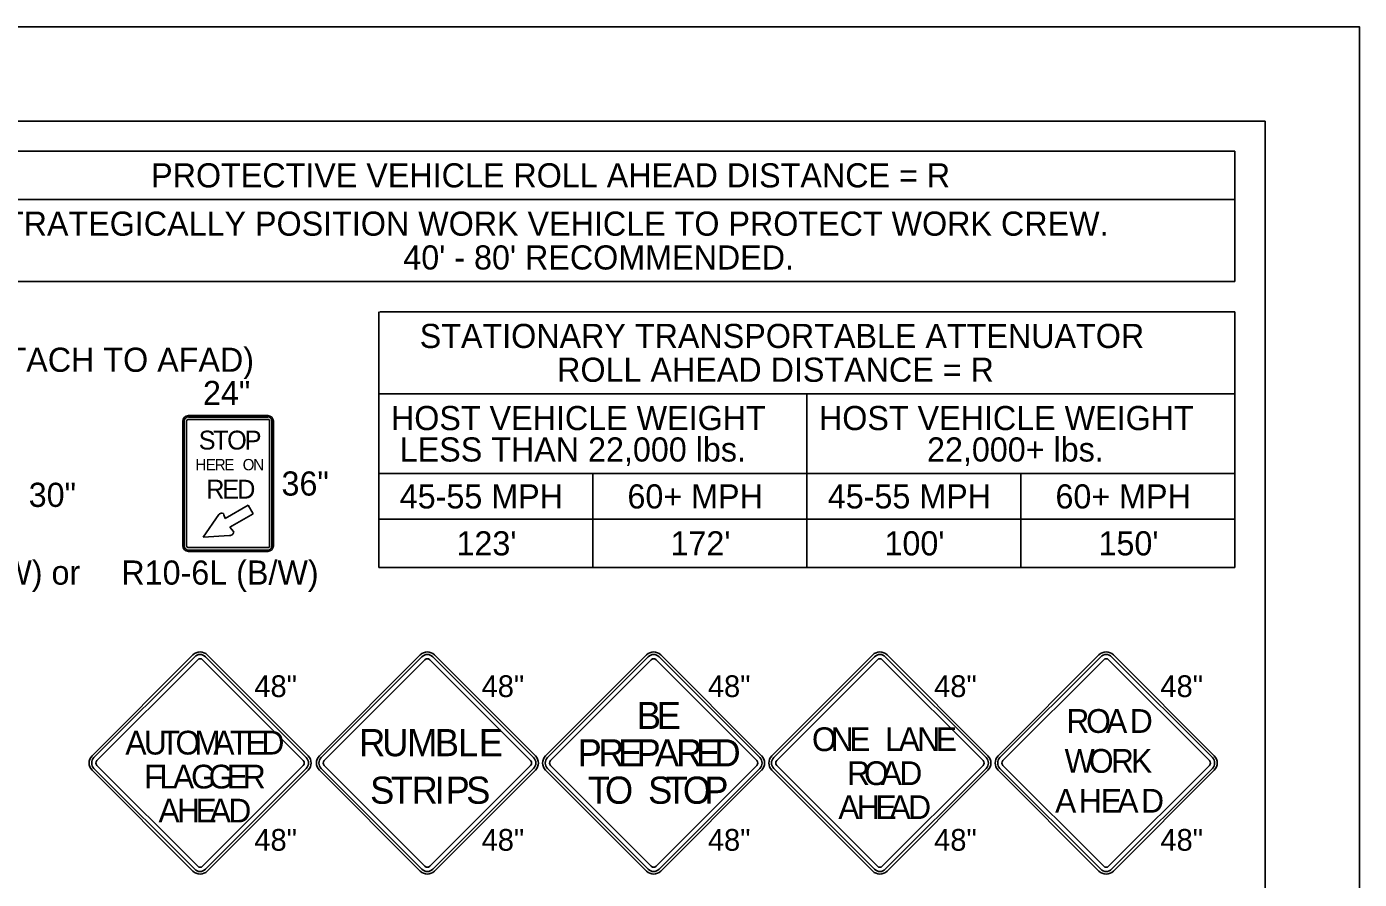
# Model space of a CAD drawing. Extents: x 99999.1 to 100095.7, y 99995 to 100010.7.
# Drawn here: x 100011.645 to 100016.062, y 100007.863 to 100010.687 of the extents above; entities that cross this region are included whole.
import ezdxf

# ---------------------------------------------------------------- set-up
doc = ezdxf.new("R2010")
doc.units = 0
for name, color, linetype in [('Default', 7, 'Continuous'), ('SH_GI_PlotLimits', 7, 'Continuous'), ('SH_GI_SheetBorder', 7, 'Continuous'), ('SH_TI_Tables', 7, 'Continuous'), ('TR_SN_ConstructionSigns', 7, 'Continuous'), ('TR_WZ_WorkZoneDetails', 7, 'Continuous')]:
    doc.layers.add(name, color=color, linetype=linetype)

msp = doc.modelspace()

# ---------------------------------------------------------------- linework, layer by layer
at = {"layer": 'Default'}
for p, q in [((100012.9495, 100008.6062), (100012.6154, 100008.2721)), ((100013.3313, 100008.2721), (100012.9972, 100008.6062)), ((100012.6154, 100008.2243), (100012.9495, 100007.8902)), ((100012.9972, 100007.8902), (100013.3313, 100008.2243))]:
    msp.add_line(p, q, dxfattribs=at)
for centre, start, end in [((100012.9733, 100008.5823), 45, 135), ((100012.6392, 100008.2482), 135, 225), ((100013.3075, 100008.2482), 315, 45), ((100012.9733, 100007.9141), 225, 315)]:
    msp.add_arc(centre, 0.0338, start, end, dxfattribs=at)
at = {"layer": 'SH_GI_PlotLimits'}
msp.add_lwpolyline([(99999.0625, 99999.6875), (100016.0625, 99999.6875), (100016.0625, 100010.6875), (99999.0625, 100010.6875)], close=True, dxfattribs=at)
at = {"layer": 'SH_GI_SheetBorder'}
for p, q in [((100000, 100010.375), (100015.75, 100010.375)), ((100015.75, 100010.375), (100015.75, 100000))]:
    msp.add_line(p, q, dxfattribs=at)
at = {"layer": 'SH_TI_Tables'}
for p, q in [((100011.4347, 100010.275), (100015.65, 100010.275)), ((100015.65, 100009.843), (100015.65, 100010.275)), ((100011.4347, 100010.115), (100015.65, 100010.115)), ((100011.4347, 100009.843), (100015.65, 100009.843)), ((100012.8126, 100008.896), (100012.8126, 100009.743)), ((100012.8156, 100009.743), (100015.65, 100009.743)), ((100015.65, 100008.896), (100015.65, 100009.743)), ((100012.8126, 100009.471), (100015.65, 100009.471)), ((100014.2313, 100008.896), (100014.2313, 100009.471)), ((100012.8126, 100009.2069), (100014.2313, 100009.2069)), ((100013.5219, 100008.896), (100013.5219, 100009.2069)), ((100014.2313, 100009.2069), (100015.65, 100009.2069)), ((100014.9406, 100008.896), (100014.9406, 100009.2069)), ((100012.8126, 100009.056), (100014.2313, 100009.056)), ((100014.2313, 100009.056), (100015.65, 100009.056)), ((100012.8126, 100008.896), (100015.65, 100008.896))]:
    msp.add_line(p, q, dxfattribs=at)
at = {"layer": 'TR_SN_ConstructionSigns'}
for p, q in [((100012.4441, 100009.3991), (100012.1816, 100009.3991)), ((100012.1816, 100009.3991), (100012.4441, 100009.3991)), ((100012.4441, 100009.3991), (100012.1816, 100009.3991)), ((100012.1629, 100009.3804), (100012.1629, 100008.9679)), ((100012.1629, 100008.9679), (100012.1629, 100009.3804)), ((100012.1629, 100009.3804), (100012.1629, 100008.9679)), ((100012.1676, 100009.3804), (100012.1676, 100008.9679)), ((100012.1754, 100008.9679), (100012.1754, 100009.3804)), ((100012.4441, 100009.3944), (100012.1816, 100009.3944)), ((100012.1816, 100009.3866), (100012.4441, 100009.3866)), ((100012.4504, 100009.3804), (100012.4504, 100008.9679)), ((100012.4582, 100008.9679), (100012.4582, 100009.3804)), ((100012.4629, 100008.9679), (100012.4629, 100009.3804)), ((100012.4629, 100009.3804), (100012.4629, 100008.9679)), ((100012.4629, 100008.9679), (100012.4629, 100009.3804)), ((100012.3796, 100009.1022), (100012.303, 100009.058)), ((100012.396, 100009.0738), (100012.3796, 100009.1022)), ((100012.2824, 100009.0718), (100012.2298, 100008.9961)), ((100012.303, 100009.058), (100012.2992, 100009.0706)), ((100012.3186, 100009.0291), (100012.396, 100009.0738)), ((100012.2298, 100008.9961), (100012.3176, 100009.0022)), ((100012.3309, 100009.0154), (100012.3186, 100009.0291)), ((100012.4441, 100008.9616), (100012.1816, 100008.9616)), ((100012.1816, 100008.9538), (100012.4441, 100008.9538)), ((100012.1816, 100008.9491), (100012.4441, 100008.9491)), ((100012.4441, 100008.9491), (100012.1816, 100008.9491)), ((100012.1816, 100008.9491), (100012.4441, 100008.9491)), ((100012.1961, 100008.6062), (100011.862, 100008.2721)), ((100012.5779, 100008.2721), (100012.2438, 100008.6062)), ((100012.6154, 100008.2721), (100012.9495, 100008.6062)), ((100012.9972, 100008.6062), (100013.3313, 100008.2721)), ((100013.3654, 100008.2721), (100013.6995, 100008.6062)), ((100013.7472, 100008.6062), (100014.0813, 100008.2721)), ((100014.1154, 100008.2721), (100014.4495, 100008.6062)), ((100014.4972, 100008.6062), (100014.8313, 100008.2721)), ((100014.8654, 100008.2721), (100015.1995, 100008.6062)), ((100015.2472, 100008.6062), (100015.5813, 100008.2721)), ((100012.2021, 100008.6002), (100011.868, 100008.2661)), ((100011.8779, 100008.2561), (100012.212, 100008.5903)), ((100012.2279, 100008.5903), (100012.562, 100008.2561)), ((100012.572, 100008.2661), (100012.2379, 100008.6002)), ((100012.9555, 100008.6002), (100012.6213, 100008.2661)), ((100012.6313, 100008.2561), (100012.9654, 100008.5903)), ((100012.9813, 100008.5903), (100013.3154, 100008.2561)), ((100013.3254, 100008.2661), (100012.9912, 100008.6002)), ((100013.7055, 100008.6002), (100013.3713, 100008.2661)), ((100013.3813, 100008.2561), (100013.7154, 100008.5903)), ((100013.7313, 100008.5903), (100014.0654, 100008.2561)), ((100014.0754, 100008.2661), (100013.7412, 100008.6002)), ((100014.4555, 100008.6002), (100014.1213, 100008.2661)), ((100014.1313, 100008.2561), (100014.4654, 100008.5903)), ((100014.4813, 100008.5903), (100014.8154, 100008.2561)), ((100014.8254, 100008.2661), (100014.4912, 100008.6002)), ((100015.2055, 100008.6002), (100014.8713, 100008.2661)), ((100014.8813, 100008.2561), (100015.2154, 100008.5903)), ((100015.2313, 100008.5903), (100015.5654, 100008.2561)), ((100015.5754, 100008.2661), (100015.2412, 100008.6002)), ((100011.862, 100008.2243), (100012.1961, 100007.8902)), ((100011.868, 100008.2303), (100012.2021, 100007.8962)), ((100012.212, 100007.9061), (100011.8779, 100008.2402)), ((100012.562, 100008.2402), (100012.2279, 100007.9061)), ((100012.2379, 100007.8962), (100012.572, 100008.2303)), ((100012.2438, 100007.8902), (100012.5779, 100008.2243)), ((100012.9495, 100007.8902), (100012.6154, 100008.2243)), ((100012.6213, 100008.2303), (100012.9555, 100007.8962)), ((100012.9654, 100007.9061), (100012.6313, 100008.2402)), ((100013.3154, 100008.2402), (100012.9813, 100007.9061)), ((100012.9912, 100007.8962), (100013.3254, 100008.2303)), ((100013.3313, 100008.2243), (100012.9972, 100007.8902)), ((100013.6995, 100007.8902), (100013.3654, 100008.2243)), ((100013.3713, 100008.2303), (100013.7055, 100007.8962)), ((100013.7154, 100007.9061), (100013.3813, 100008.2402)), ((100014.0654, 100008.2402), (100013.7313, 100007.9061)), ((100013.7412, 100007.8962), (100014.0754, 100008.2303)), ((100014.0813, 100008.2243), (100013.7472, 100007.8902)), ((100014.4495, 100007.8902), (100014.1154, 100008.2243)), ((100014.1213, 100008.2303), (100014.4555, 100007.8962)), ((100014.4654, 100007.9061), (100014.1313, 100008.2402)), ((100014.8154, 100008.2402), (100014.4813, 100007.9061)), ((100014.4912, 100007.8962), (100014.8254, 100008.2303)), ((100014.8313, 100008.2243), (100014.4972, 100007.8902)), ((100015.1995, 100007.8902), (100014.8654, 100008.2243)), ((100014.8713, 100008.2303), (100015.2055, 100007.8962)), ((100015.2154, 100007.9061), (100014.8813, 100008.2402)), ((100015.5654, 100008.2402), (100015.2313, 100007.9061)), ((100015.2412, 100007.8962), (100015.5754, 100008.2303)), ((100015.5813, 100008.2243), (100015.2472, 100007.8902))]:
    msp.add_line(p, q, dxfattribs=at)
for centre, radius, start, end in [((100012.1816, 100009.3804), 0.0187, 90, 180), ((100012.1816, 100009.3804), 0.0187, 90, 180), ((100012.1816, 100009.3804), 0.0187, 90, 180), ((100012.4441, 100009.3804), 0.0187, 0, 90), ((100012.4441, 100009.3804), 0.0187, 0, 90), ((100012.4441, 100009.3804), 0.0187, 0, 90), ((100012.1816, 100009.3804), 0.0141, 90, 180), ((100012.1816, 100009.3804), 0.00625, 90, 180), ((100012.4441, 100009.3804), 0.0141, 0, 90), ((100012.4441, 100009.3804), 0.00625, 0, 90), ((100012.1816, 100008.9679), 0.0187, 180, 270), ((100012.1816, 100008.9679), 0.0187, 180, 270), ((100012.1816, 100008.9679), 0.0187, 180, 270), ((100012.1816, 100008.9679), 0.0141, 180, 270), ((100012.1816, 100008.9679), 0.00625, 180, 270), ((100012.4441, 100008.9679), 0.0187, 270, 0), ((100012.4441, 100008.9679), 0.0187, 270, 0), ((100012.4441, 100008.9679), 0.0187, 270, 0), ((100012.4441, 100008.9679), 0.0141, 270, 0), ((100012.4441, 100008.9679), 0.00625, 270, 0), ((100012.22, 100008.5823), 0.0338, 45, 135), ((100012.22, 100008.5823), 0.0253, 45, 135), ((100012.9733, 100008.5823), 0.0338, 45, 135), ((100012.9733, 100008.5823), 0.0253, 45, 135), ((100013.7233, 100008.5823), 0.0338, 45, 135), ((100013.7233, 100008.5823), 0.0253, 45, 135), ((100014.4733, 100008.5823), 0.0338, 45, 135), ((100014.4733, 100008.5823), 0.0253, 45, 135), ((100015.2233, 100008.5823), 0.0338, 45, 135), ((100015.2233, 100008.5823), 0.0253, 45, 135), ((100012.22, 100008.5823), 0.0113, 45, 135), ((100012.9733, 100008.5823), 0.0113, 45, 135), ((100013.7233, 100008.5823), 0.0113, 45, 135), ((100014.4733, 100008.5823), 0.0113, 45, 135), ((100015.2233, 100008.5823), 0.0113, 45, 135), ((100011.8859, 100008.2482), 0.0338, 135, 225), ((100011.8859, 100008.2482), 0.0253, 135, 225), ((100011.8859, 100008.2482), 0.0113, 135, 225), ((100012.5541, 100008.2482), 0.0113, 315, 45), ((100012.5541, 100008.2482), 0.0253, 315, 45), ((100012.5541, 100008.2482), 0.0338, 315, 45), ((100012.6392, 100008.2482), 0.0338, 135, 225), ((100012.6392, 100008.2482), 0.0253, 135, 225), ((100012.6392, 100008.2482), 0.0113, 135, 225), ((100013.3075, 100008.2482), 0.0113, 315, 45), ((100013.3075, 100008.2482), 0.0253, 315, 45), ((100013.3075, 100008.2482), 0.0338, 315, 45), ((100013.3892, 100008.2482), 0.0338, 135, 225), ((100013.3892, 100008.2482), 0.0253, 135, 225), ((100013.3892, 100008.2482), 0.0113, 135, 225), ((100014.0575, 100008.2482), 0.0113, 315, 45), ((100014.0575, 100008.2482), 0.0253, 315, 45), ((100014.0575, 100008.2482), 0.0338, 315, 45), ((100014.1392, 100008.2482), 0.0338, 135, 225), ((100014.1392, 100008.2482), 0.0253, 135, 225), ((100014.1392, 100008.2482), 0.0113, 135, 225), ((100014.8075, 100008.2482), 0.0113, 315, 45), ((100014.8075, 100008.2482), 0.0253, 315, 45), ((100014.8075, 100008.2482), 0.0338, 315, 45), ((100014.8892, 100008.2482), 0.0338, 135, 225), ((100014.8892, 100008.2482), 0.0253, 135, 225), ((100014.8892, 100008.2482), 0.0113, 135, 225), ((100015.5575, 100008.2482), 0.0113, 315, 45), ((100015.5575, 100008.2482), 0.0253, 315, 45), ((100015.5575, 100008.2482), 0.0338, 315, 45), ((100012.22, 100007.9141), 0.0113, 225, 315), ((100012.9733, 100007.9141), 0.0113, 225, 315), ((100013.7233, 100007.9141), 0.0113, 225, 315), ((100014.4733, 100007.9141), 0.0113, 225, 315), ((100015.2233, 100007.9141), 0.0113, 225, 315), ((100012.22, 100007.9141), 0.0338, 225, 315), ((100012.22, 100007.9141), 0.0253, 225, 315), ((100012.9733, 100007.9141), 0.0338, 225, 315), ((100012.9733, 100007.9141), 0.0253, 225, 315), ((100013.7233, 100007.9141), 0.0338, 225, 315), ((100013.7233, 100007.9141), 0.0253, 225, 315), ((100014.4733, 100007.9141), 0.0338, 225, 315), ((100014.4733, 100007.9141), 0.0253, 225, 315), ((100015.2233, 100007.9141), 0.0338, 225, 315), ((100015.2233, 100007.9141), 0.0253, 225, 315)]:
    msp.add_arc(centre, radius, start, end, dxfattribs=at)
for centre, major_axis, start_param, end_param in [((100012.2891, 100009.0675), (0.00934, 0.00539), 5.977036, 8.198856), ((100012.3216, 100009.0104), (-0.00913, -0.00527), 0.771965, 3.092601)]:
    msp.add_ellipse(centre, major_axis=major_axis, ratio=0.700347, start_param=start_param, end_param=end_param, dxfattribs=at)
at = {"layer": 'TR_WZ_WorkZoneDetails'}
for p, q in [((100013.6995, 100008.6062), (100013.3654, 100008.2721)), ((100014.0813, 100008.2721), (100013.7472, 100008.6062)), ((100014.4495, 100008.6062), (100014.1154, 100008.2721)), ((100014.8313, 100008.2721), (100014.4972, 100008.6062)), ((100015.1995, 100008.6062), (100014.8654, 100008.2721)), ((100015.5813, 100008.2721), (100015.2472, 100008.6062)), ((100013.3654, 100008.2243), (100013.6995, 100007.8902)), ((100013.7472, 100007.8902), (100014.0813, 100008.2243)), ((100014.1154, 100008.2243), (100014.4495, 100007.8902)), ((100014.4972, 100007.8902), (100014.8313, 100008.2243)), ((100014.8654, 100008.2243), (100015.1995, 100007.8902)), ((100015.2472, 100007.8902), (100015.5813, 100008.2243))]:
    msp.add_line(p, q, dxfattribs=at)
for centre, start, end in [((100013.7233, 100008.5823), 45, 135), ((100014.4733, 100008.5823), 45, 135), ((100015.2233, 100008.5823), 45, 135), ((100013.3892, 100008.2482), 135, 225), ((100014.0575, 100008.2482), 315, 45), ((100014.1392, 100008.2482), 135, 225), ((100014.8075, 100008.2482), 315, 45), ((100014.8892, 100008.2482), 135, 225), ((100015.5575, 100008.2482), 315, 45), ((100013.7233, 100007.9141), 225, 315), ((100014.4733, 100007.9141), 225, 315), ((100015.2233, 100007.9141), 225, 315)]:
    msp.add_arc(centre, 0.0338, start, end, dxfattribs=at)

# ---------------------------------------------------------------- texts
at = {"layer": 'Default'}
for s, p in [('R', (100012.747, 100008.2707)), ('U', (100012.8235, 100008.2707)), ('M', (100012.9063, 100008.2707)), ('B', (100012.9981, 100008.2707)), ('L', (100013.0746, 100008.2707)), ('E', (100013.1439, 100008.2707)), ('S', (100012.7834, 100008.1132)), ('T', (100012.8518, 100008.1132)), ('R', (100012.9211, 100008.1132)), ('I', (100012.9976, 100008.1132)), ('P', (100013.0336, 100008.1132)), ('S', (100013.102, 100008.1132))]:
    msp.add_text(s, height=0.09, dxfattribs=at).set_placement(p)
at = {"layer": 'SH_TI_Tables'}
for s, p in [('PROTECTIVE VEHICLE ROLL AHEAD DISTANCE = R', (100012.0577, 100010.155)), ('STRATEGICALLY POSITION WORK VEHICLE TO PROTECT WORK CREW.', (100011.4984, 100009.995)), ("40' - 80'", (100012.8935, 100009.883)), ('RECOMMENDED.', (100013.297, 100009.883)), ('STATIONARY TRANSPORTABLE ATTENUATOR', (100012.9479, 100009.623)), ('ROLL AHEAD DISTANCE = R', (100013.4035, 100009.511)), ('HOST VEHICLE WEIGHT', (100012.8526, 100009.351)), ('HOST VEHICLE WEIGHT', (100014.2713, 100009.351)), ('LESS THAN 22,000 lbs.', (100012.8817, 100009.2469)), ('22,000+ lbs.', (100014.6295, 100009.2469)), ('45-55 MPH', (100012.8818, 100009.0914)), ('60+ MPH', (100013.6365, 100009.0914)), ('45-55 MPH', (100014.3006, 100009.0914)), ('60+ MPH', (100015.0552, 100009.0914)), ("123'", (100013.0698, 100008.936)), ("172'", (100013.7792, 100008.936)), ("100'", (100014.4885, 100008.936)), ("150'", (100015.1979, 100008.936))]:
    msp.add_text(s, height=0.08, dxfattribs=at).set_placement(p)
at = {"layer": 'TR_SN_ConstructionSigns'}
for s, height, p in [('(MAY ATTACH TO AFAD)', 0.08, (100011.1446, 100009.5441)), ('24"', 0.08, (100012.2295, 100009.4341)), ('36"', 0.08, (100012.4898, 100009.1341)), ('30"', 0.08, (100011.6518, 100009.0966)), ('R10-6A (B/W) or', 0.08, (100011.032, 100008.8391)), ('R10-6L (B/W)', 0.08, (100011.959, 100008.8391)), ('48"', 0.072, (100012.3998, 100008.4667)), ('48"', 0.072, (100013.1531, 100008.4667)), ('48"', 0.072, (100013.9031, 100008.4667)), ('48"', 0.072, (100014.6531, 100008.4667)), ('48"', 0.072, (100015.4031, 100008.4667)), ('48"', 0.072, (100012.3998, 100007.9576)), ('48"', 0.072, (100013.1531, 100007.9576)), ('48"', 0.072, (100013.9031, 100007.9576)), ('48"', 0.072, (100014.6531, 100007.9576)), ('48"', 0.072, (100015.4031, 100007.9576))]:
    msp.add_text(s, height=height, rotation=360, dxfattribs=at).set_placement(p)
for s, height, p in [('S', 0.0625, (100012.2154, 100009.2866)), ('T', 0.0625, (100012.2629, 100009.2866)), ('O', 0.0625, (100012.3097, 100009.2866)), ('P', 0.0625, (100012.3679, 100009.2866)), ('H', 0.0375, (100012.2043, 100009.2179)), ('E', 0.0375, (100012.2388, 100009.2179)), ('R', 0.0375, (100012.2684, 100009.2179)), ('E', 0.0375, (100012.3003, 100009.2179)), ('O', 0.0375, (100012.3611, 100009.2179)), ('N', 0.0375, (100012.3959, 100009.2179)), ('R', 0.0625, (100012.2404, 100009.1241)), ('E', 0.0625, (100012.2935, 100009.1241)), ('D', 0.0625, (100012.3429, 100009.1241)), ('A', 0.0787, (100011.9723, 100008.2763)), ('U', 0.0787, (100012.0337, 100008.2763)), ('T', 0.0787, (100012.0888, 100008.2763)), ('O', 0.0787, (100012.1385, 100008.2763)), ('M', 0.0787, (100012.2007, 100008.2763)), ('A', 0.0787, (100012.2637, 100008.2763)), ('T', 0.0787, (100012.3188, 100008.2763)), ('E', 0.0787, (100012.37, 100008.2763)), ('D', 0.0787, (100012.4235, 100008.2763)), ('F', 0.0787, (100012.0341, 100008.1638)), ('L', 0.0787, (100012.0853, 100008.1638)), ('A', 0.0787, (100012.1302, 100008.1638)), ('G', 0.0787, (100012.19, 100008.1638)), ('G', 0.0787, (100012.2483, 100008.1638)), ('E', 0.0787, (100012.3082, 100008.1638)), ('R', 0.0787, (100012.3617, 100008.1638)), ('A', 0.0787, (100012.0821, 100008.0513)), ('H', 0.0787, (100012.1436, 100008.0513)), ('E', 0.0787, (100012.205, 100008.0513)), ('A', 0.0787, (100012.2522, 100008.0513)), ('D', 0.0787, (100012.3137, 100008.0513))]:
    msp.add_text(s, height=height, dxfattribs=at).set_placement(p)
at = {"layer": 'TR_WZ_WorkZoneDetails'}
for s, height, p in [('B', 0.09, (100013.6675, 100008.3607)), ('E', 0.09, (100013.7332, 100008.3607)), ('O', 0.0788, (100015.1568, 100008.348)), ('R', 0.0788, (100015.0914, 100008.348)), ('A', 0.0788, (100015.223, 100008.348)), ('D', 0.0788, (100015.3017, 100008.348)), ('O', 0.0787, (100014.2481, 100008.2876)), ('N', 0.0787, (100014.3103, 100008.2876)), ('E', 0.0787, (100014.3718, 100008.2876)), ('L', 0.0787, (100014.4907, 100008.2876)), ('A', 0.0787, (100014.5356, 100008.2876)), ('N', 0.0787, (100014.597, 100008.2876)), ('E', 0.0787, (100014.6584, 100008.2876)), ('P', 0.09, (100013.4713, 100008.2369)), ('R', 0.09, (100013.5397, 100008.2369)), ('E', 0.09, (100013.6054, 100008.2369)), ('P', 0.09, (100013.6666, 100008.2369)), ('A', 0.09, (100013.7278, 100008.2369)), ('R', 0.09, (100013.798, 100008.2369)), ('E', 0.09, (100013.8637, 100008.2369)), ('D', 0.09, (100013.9249, 100008.2369)), ('O', 0.0788, (100015.1659, 100008.2158)), ('R', 0.0787, (100014.3647, 100008.1751)), ('O', 0.0787, (100014.4206, 100008.1751)), ('A', 0.0787, (100014.4765, 100008.1751)), ('D', 0.0787, (100014.5379, 100008.1751)), ('W', 0.0788, (100015.0855, 100008.2158)), ('R', 0.0788, (100015.2391, 100008.2158)), ('K', 0.0788, (100015.306, 100008.2158)), ('T', 0.09, (100013.5051, 100008.1132)), ('O', 0.09, (100013.5618, 100008.1132)), ('S', 0.09, (100013.7049, 100008.1132)), ('T', 0.09, (100013.7634, 100008.1132)), ('O', 0.09, (100013.8201, 100008.1132)), ('P', 0.09, (100013.8912, 100008.1132)), ('A', 0.0788, (100015.054, 100008.0837)), ('H', 0.0788, (100015.1328, 100008.0837)), ('E', 0.0788, (100015.2052, 100008.0837)), ('A', 0.0788, (100015.2604, 100008.0837)), ('D', 0.0788, (100015.3391, 100008.0837)), ('A', 0.0787, (100014.3355, 100008.0626)), ('H', 0.0787, (100014.397, 100008.0626)), ('E', 0.0787, (100014.4584, 100008.0626)), ('A', 0.0787, (100014.5056, 100008.0626)), ('D', 0.0787, (100014.5671, 100008.0626))]:
    msp.add_text(s, height=height, dxfattribs=at).set_placement(p)

doc.saveas('drawing.dxf')
